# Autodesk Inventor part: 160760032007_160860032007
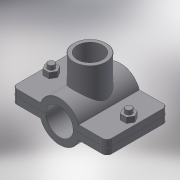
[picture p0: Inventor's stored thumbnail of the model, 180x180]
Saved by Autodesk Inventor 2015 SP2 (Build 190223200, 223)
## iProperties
Created: 2017-05
Part Number: 160760032007_160860032007
Material: Generic
Description: PLASSON SADDLE 32-3/4"
Document SubType Name: Modeling
Designer: KIM
Density: 1 g/cm^3
Appearance: Default
Author: KIM
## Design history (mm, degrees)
derived "16076.ipt"
feature "Solid1::16076.ipt"
feature "Solid2::16076.ipt"
tag "TaggingFeature1"
body "Solid1"
other parameters: "d0" = 48, "d1" = 92, "d2" = 16, "d3" = 32, "d5" = 0, "d6" = 4.6, "d7" = 92, "d8" = 0.1, "d10" = 0, "d11" = 0.32, "d14" = 31.3521, "d20" = 0.32, "d23" = 0.32, "d37" = 8, "d38" = 24, "d39" = 0, "d40" = 3, "d41" = 5, "d42" = 0, "d43" = 6, "d44" = 3, "d45" = 0, "d46" = 0.32, "d51" = 41, "d52" = 24.117, "d53" = 19, "d54" = 0, "d55" = 19, "d57" = 0, "d58" = 34.56, "d60" = 0, "d66" = 0, "d_" = 32, "B_" = 19, "G_" = 24.117, "A_" = 41, "L_" = 92, "l_2" = 19
